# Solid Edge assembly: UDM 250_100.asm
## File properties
Title: Zylinder
Author: ahadarics
Template: iso assembly.asm
Last saved by: ahadarics
Revision: 29
Application: Solid Edge
Username: ahadarics
Dokumentum tartalom típus: 1
Document Number: UDM 250/100
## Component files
Kit_1.par
Profilrohr 250_100.par
Zugstange 250_100.par
Kit_2.par
Mutter.par
Kolbenstange 250_100.par
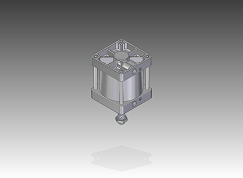
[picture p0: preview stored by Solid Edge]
